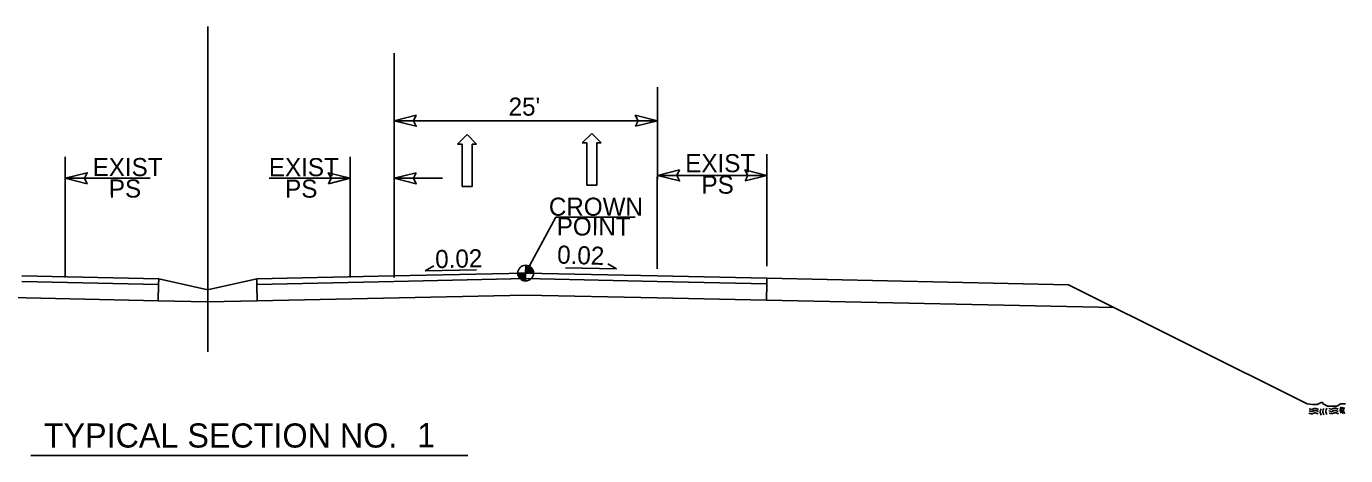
# Model space of a CAD drawing. Extents: x 2241081 to 2251104, y 658534 to 663427.
# Drawn here: x 2241521 to 2242122, y 662176 to 662372 of the extents above; entities that cross this region are included whole.
import ezdxf

# ---------------------------------------------------------------- set-up
doc = ezdxf.new("R2010")
doc.units = 0
for name, color, linetype in [('Old_Level_1', 7, 'Continuous'), ('Old_Level_2', 7, 'Continuous'), ('Prop Dimension Text', 7, 'Continuous'), ('Prop Lane Arrow CELL', 7, 'Continuous'), ('Typical Arrow Superelevation CELL', 7, 'Continuous'), ('Typical Berm Information CELL', 7, 'Continuous'), ('Typical Grade Point Symbol CELL', 7, 'Continuous'), ('Typical Hinge Slope Interstate CELL', 7, 'Continuous'), ('Typical Terminator CELL', 7, 'Continuous'), ('Typical Text Centerline CELL', 7, 'Continuous'), ('Typical Text Grade Point CELL', 7, 'Continuous'), ('Typical Text Label CELL', 7, 'Continuous')]:
    doc.layers.add(name, color=color, linetype=linetype)

# ---------------------------------------------------------------- blocks, each defined once
blk = doc.blocks.new('TERMINATOR')
at = {"layer": 'Typical Terminator CELL'}
blk.add_lwpolyline([(-0.469, 0.081), (0, 0), (-0.471, -0.083), (-0.411, 0)], close=True, dxfattribs=at)

msp = doc.modelspace()

# ---------------------------------------------------------------- linework, layer by layer
at = {"layer": 'Old_Level_1'}
for p, q in [((2241581.23, 662256.58), (2241603.63, 662251.64)), ((2241625.93, 662256.58), (2241603.53, 662251.64))]:
    msp.add_line(p, q, dxfattribs=at)
msp.add_lwpolyline([(2242104.86, 662199.5), (2242107.33, 662199.19), (2242107.94, 662199.19), (2242108.87, 662199.19), (2242109.48, 662199.19), (2242110.1, 662199.5), (2242110.72, 662199.81), (2242111.33, 662200.11), (2242111.95, 662200.11), (2242112.26, 662199.5), (2242112.87, 662199.19), (2242113.49, 662198.88), (2242114.11, 662198.57), (2242114.72, 662198.57), (2242115.34, 662198.57), (2242115.95, 662198.57), (2242116.57, 662198.57), (2242117.19, 662198.57), (2242117.8, 662198.57), (2242118.42, 662198.57), (2242119.03, 662198.88), (2242119.65, 662199.19), (2242120.27, 662199.5), (2242121.19, 662199.5), (2242121.81, 662199.5), (2242122.42, 662199.5)], dxfattribs=at)
at = {"layer": 'Old_Level_2'}
for p, q in [((2241518.84, 662257.92), (2241581.23, 662256.58)), ((2241581.23, 662256.58), (2241581.18, 662254.08)), ((2241688.32, 662257.92), (2241625.93, 662256.58)), ((2241625.93, 662256.58), (2241625.98, 662254.08)), ((2241748.54, 662259.21), (2241688.32, 662257.92)), ((2241748.59, 662256.71), (2241688.37, 662255.42)), ((2241748.49, 662256.71), (2241808.54, 662255.42)), ((2241748.54, 662259.21), (2241808.54, 662257.92)), ((2241808.54, 662257.92), (2241858.54, 662256.85)), ((2241858.54, 662256.85), (2241858.48, 662254.35)), ((2241858.54, 662256.85), (2241996.04, 662253.91)), ((2241518.79, 662255.42), (2241581.18, 662254.08)), ((2241581.02, 662246.59), (2241581.18, 662254.08)), ((2241688.37, 662255.42), (2241625.98, 662254.08)), ((2241626.14, 662246.59), (2241625.98, 662254.08)), ((2241808.54, 662255.42), (2241858.48, 662254.35)), ((2241858.32, 662246.85), (2241858.48, 662254.35)), ((2241458.63, 662249.21), (2241581.02, 662246.59)), ((2241581.02, 662246.59), (2241603.58, 662246.1)), ((2241626.14, 662246.59), (2241603.58, 662246.1)), ((2241748.53, 662249.21), (2241626.14, 662246.59)), ((2241748.53, 662249.21), (2241808.53, 662247.92)), ((2241808.53, 662247.92), (2241858.32, 662246.85)), ((2241858.32, 662246.85), (2242016.93, 662243.46))]:
    msp.add_line(p, q, dxfattribs=at)
for points in [[(2242109.84, 662194.99), (2242108.34, 662195.41), (2242106.75, 662195.01), (2242105.6, 662195.27)], [(2242109.99, 662196.08), (2242108.49, 662196.51), (2242106.9, 662196.1), (2242105.75, 662196.36)], [(2242109.99, 662196.08), (2242108.49, 662196.51), (2242106.9, 662196.1), (2242105.75, 662196.36)], [(2242110.03, 662197.02), (2242108.53, 662197.45), (2242106.94, 662197.04), (2242105.79, 662197.3)], [(2242110.03, 662197.02), (2242108.53, 662197.45), (2242106.94, 662197.04), (2242105.79, 662197.3)], [(2242111.28, 662197.31), (2242110.85, 662196.06), (2242111.31, 662194.42)], [(2242111.28, 662197.31), (2242110.85, 662196.06), (2242111.31, 662194.42)], [(2242112.49, 662197.42), (2242112.07, 662196.17), (2242112.52, 662194.52)], [(2242112.49, 662197.42), (2242112.07, 662196.17), (2242112.52, 662194.52)], [(2242113.8, 662197.52), (2242113.39, 662196.28), (2242113.83, 662194.63)], [(2242113.8, 662197.52), (2242113.39, 662196.28), (2242113.83, 662194.63)], [(2242119.06, 662197.16), (2242117.56, 662197.6), (2242115.97, 662197.19), (2242114.83, 662197.45)], [(2242119.06, 662197.16), (2242117.56, 662197.6), (2242115.97, 662197.19), (2242114.83, 662197.45)], [(2242119.07, 662196.12), (2242117.56, 662196.54), (2242115.98, 662196.14), (2242114.84, 662196.39)], [(2242119.07, 662196.12), (2242117.56, 662196.54), (2242115.98, 662196.14), (2242114.84, 662196.39)], [(2242119.19, 662195.06), (2242117.68, 662195.48), (2242116.09, 662195.09), (2242114.94, 662195.34)], [(2242119.19, 662195.06), (2242117.68, 662195.48), (2242116.09, 662195.09), (2242114.94, 662195.34)], [(2242120.39, 662198.13), (2242119.96, 662196.89), (2242120.42, 662195.24)], [(2242120.39, 662198.13), (2242119.96, 662196.89), (2242120.42, 662195.24)], [(2242121.17, 662198.05), (2242120.75, 662196.81), (2242121.21, 662195.16)], [(2242121.17, 662198.05), (2242120.75, 662196.81), (2242121.21, 662195.16)], [(2242121.9, 662197.91), (2242121.48, 662196.67), (2242121.93, 662195.02)], [(2242121.9, 662197.91), (2242121.48, 662196.67), (2242121.93, 662195.02)]]:
    msp.add_spline(points, degree=3, dxfattribs=at)
at = {"layer": 'Prop Dimension Text'}
for p, q in [((2241688.54, 662257.22), (2241688.6, 662359.56)), ((2241808.54, 662262.36), (2241808.59, 662343.98)), ((2241808.54, 662261.11), (2241808.59, 662342.73)), ((2241688.58, 662328.74), (2241748.58, 662328.7)), ((2241748.58, 662328.7), (2241808.58, 662328.66)), ((2241538.63, 662257.23), (2241538.59, 662312.31)), ((2241668.54, 662257.23), (2241668.57, 662312.31)), ((2241858.54, 662262.33), (2241858.57, 662313.44)), ((2241808.69, 662303.78), (2241858.57, 662303.75)), ((2241538.6, 662302.48), (2241577.29, 662302.5)), ((2241668.57, 662302.48), (2241631.62, 662302.5)), ((2241710.63, 662302.45), (2241688.57, 662302.47))]:
    msp.add_line(p, q, dxfattribs=at)
at = {"layer": 'Prop Lane Arrow CELL'}
for p, q in [((2241721.89, 662322.42), (2241717.48, 662318.08)), ((2241726.16, 662318.07), (2241721.89, 662322.42)), ((2241778.73, 662322.95), (2241774.32, 662318.61)), ((2241783, 662318.61), (2241778.73, 662322.95)), ((2241717.48, 662318.08), (2241719.54, 662318.08)), ((2241719.54, 662318.08), (2241719.53, 662298.78)), ((2241724.08, 662298.78), (2241724.09, 662318.08)), ((2241724.09, 662318.08), (2241726.16, 662318.07)), ((2241774.32, 662318.61), (2241776.38, 662318.61)), ((2241776.38, 662318.61), (2241776.37, 662299.31)), ((2241780.92, 662299.31), (2241780.93, 662318.61)), ((2241780.93, 662318.61), (2241783, 662318.61)), ((2241719.53, 662298.78), (2241724.08, 662298.78)), ((2241776.37, 662299.31), (2241780.92, 662299.31))]:
    msp.add_line(p, q, dxfattribs=at)
at = {"layer": 'Typical Arrow Superelevation CELL'}
for p, q in [((2241702.79, 662260.22), (2241706.7, 662262.59)), ((2241789.94, 662261.14), (2241766.64, 662261.61)), ((2241789.94, 662261.14), (2241786.03, 662263.51)), ((2241702.79, 662260.22), (2241726.09, 662260.69))]:
    msp.add_line(p, q, dxfattribs=at)
at = {"layer": 'Typical Grade Point Symbol CELL'}
for p, q in [((2241748.54, 662259.21), (2241762.31, 662284.76)), ((2241748.55, 662262.79), (2241748.54, 662259.21)), ((2241748.54, 662259.21), (2241748.55, 662262.79)), ((2241744.96, 662259.21), (2241748.54, 662259.21)), ((2241748.54, 662259.21), (2241748.54, 662255.63)), ((2241752.12, 662259.21), (2241748.54, 662259.21))]:
    msp.add_line(p, q, dxfattribs=at)
for points in [[(2241748.59, 662259.21), (2241748.59, 662262.79), (2241748.59, 662262.79)], [(2241748.67, 662259.21), (2241748.67, 662262.79)], [(2241748.74, 662259.21), (2241748.74, 662262.78)], [(2241748.81, 662259.21), (2241748.81, 662262.78)], [(2241748.88, 662259.21), (2241748.88, 662262.77)], [(2241748.95, 662259.21), (2241748.95, 662262.76)], [(2241749.02, 662259.21), (2241749.02, 662262.76)], [(2241749.1, 662259.21), (2241749.1, 662262.74)], [(2241749.17, 662259.21), (2241749.17, 662262.73)], [(2241749.24, 662259.21), (2241749.24, 662262.72)], [(2241749.31, 662259.21), (2241749.31, 662262.7)], [(2241749.38, 662259.21), (2241749.38, 662262.68)], [(2241749.45, 662259.21), (2241749.45, 662262.67)], [(2241749.53, 662259.21), (2241749.53, 662262.65)], [(2241749.6, 662259.21), (2241749.6, 662262.63)], [(2241749.67, 662259.21), (2241749.67, 662262.61)], [(2241749.74, 662259.21), (2241749.74, 662262.58)], [(2241749.81, 662259.21), (2241749.81, 662262.56)], [(2241749.88, 662259.21), (2241749.88, 662262.53)], [(2241749.96, 662259.21), (2241749.96, 662262.49)], [(2241750.03, 662259.21), (2241750.03, 662262.46)], [(2241750.1, 662259.21), (2241750.1, 662262.43)], [(2241750.17, 662259.21), (2241750.17, 662262.4)], [(2241750.24, 662259.21), (2241750.24, 662262.36)], [(2241750.31, 662259.21), (2241750.31, 662262.32)], [(2241750.38, 662259.21), (2241750.38, 662262.28)], [(2241750.46, 662259.21), (2241750.46, 662262.23)], [(2241750.53, 662259.21), (2241750.53, 662262.18)], [(2241750.6, 662259.21), (2241750.6, 662262.14)], [(2241750.67, 662259.21), (2241750.67, 662262.09)], [(2241750.74, 662259.21), (2241750.74, 662262.03)], [(2241750.81, 662259.21), (2241750.81, 662261.98)], [(2241750.89, 662259.21), (2241750.89, 662261.91)], [(2241750.96, 662259.21), (2241750.96, 662261.85)], [(2241751.03, 662259.21), (2241751.03, 662261.79)], [(2241751.1, 662259.21), (2241751.1, 662261.71)], [(2241751.17, 662259.21), (2241751.17, 662261.63)], [(2241751.24, 662259.21), (2241751.24, 662261.55)], [(2241745, 662258.7), (2241745, 662259.21)], [(2241745.07, 662258.33), (2241745.07, 662259.21)], [(2241745.14, 662258.09), (2241745.14, 662259.21)], [(2241745.21, 662257.89), (2241745.21, 662259.21)], [(2241745.28, 662257.72), (2241745.28, 662259.21)], [(2241745.36, 662257.57), (2241745.36, 662259.21)], [(2241745.43, 662257.44), (2241745.43, 662259.21)], [(2241745.5, 662257.32), (2241745.5, 662259.21)], [(2241745.57, 662257.21), (2241745.57, 662259.21)], [(2241745.64, 662257.11), (2241745.64, 662259.21)], [(2241745.71, 662257.01), (2241745.71, 662259.21)], [(2241745.79, 662256.92), (2241745.79, 662259.21)], [(2241745.86, 662256.84), (2241745.86, 662259.21)], [(2241745.93, 662256.76), (2241745.93, 662259.21)], [(2241746, 662256.69), (2241746, 662259.21)], [(2241746.07, 662256.61), (2241746.07, 662259.21)], [(2241746.14, 662256.55), (2241746.14, 662259.21)], [(2241746.22, 662256.49), (2241746.22, 662259.21)], [(2241746.29, 662256.42), (2241746.29, 662259.21)], [(2241746.36, 662256.37), (2241746.36, 662259.21)], [(2241746.43, 662256.32), (2241746.43, 662259.21)], [(2241746.5, 662256.26), (2241746.5, 662259.21)], [(2241746.57, 662256.22), (2241746.57, 662259.21)], [(2241746.65, 662256.17), (2241746.65, 662259.21)], [(2241746.72, 662256.13), (2241746.72, 662259.21)], [(2241746.79, 662256.09), (2241746.79, 662259.21)], [(2241746.86, 662256.05), (2241746.86, 662259.21)], [(2241746.93, 662256.01), (2241746.93, 662259.21)], [(2241747, 662255.98), (2241747, 662259.21)], [(2241747.07, 662255.95), (2241747.07, 662259.21)], [(2241747.15, 662255.91), (2241747.15, 662259.21)], [(2241747.22, 662255.88), (2241747.22, 662259.21)], [(2241747.29, 662255.85), (2241747.29, 662259.21)], [(2241747.36, 662255.83), (2241747.36, 662259.21)], [(2241747.43, 662255.8), (2241747.43, 662259.21)], [(2241747.5, 662255.78), (2241747.5, 662259.21)], [(2241747.58, 662255.76), (2241747.58, 662259.21)], [(2241747.65, 662255.74), (2241747.65, 662259.21)], [(2241747.72, 662255.72), (2241747.72, 662259.21)], [(2241747.79, 662255.71), (2241747.79, 662259.21)], [(2241747.86, 662255.69), (2241747.86, 662259.21)], [(2241747.93, 662255.67), (2241747.93, 662259.21)], [(2241748.01, 662255.67), (2241748.01, 662259.21)], [(2241748.08, 662255.66), (2241748.08, 662259.21)], [(2241748.15, 662255.65), (2241748.15, 662259.21)], [(2241748.22, 662255.64), (2241748.22, 662259.21)], [(2241748.29, 662255.63), (2241748.29, 662259.21)], [(2241748.36, 662255.63), (2241748.36, 662259.21)], [(2241748.44, 662255.63), (2241748.44, 662259.21)], [(2241748.51, 662255.63), (2241748.51, 662255.63), (2241748.51, 662259.21)], [(2241751.32, 662259.21), (2241751.32, 662261.47)], [(2241751.39, 662259.21), (2241751.39, 662261.38)], [(2241751.46, 662259.21), (2241751.46, 662261.28)], [(2241751.53, 662259.21), (2241751.53, 662261.18)], [(2241751.6, 662259.21), (2241751.6, 662261.07)], [(2241751.67, 662259.21), (2241751.67, 662260.94)], [(2241751.75, 662259.21), (2241751.75, 662260.81)], [(2241751.82, 662259.21), (2241751.82, 662260.66)], [(2241751.89, 662259.21), (2241751.89, 662260.49)], [(2241751.96, 662259.21), (2241751.96, 662260.27)], [(2241752.03, 662259.21), (2241752.03, 662260.02)], [(2241752.1, 662259.21), (2241752.1, 662259.6)]]:
    msp.add_lwpolyline(points, dxfattribs=at)
msp.add_circle((2241748.54, 662259.21), 3.58, dxfattribs=at)
for start, end in [(359.99048, 89.99048), (179.99048, 269.99048)]:
    msp.add_arc((2241748.54, 662259.21), 3.58, start, end, dxfattribs=at)
at = {"layer": 'Typical Hinge Slope Interstate CELL'}
msp.add_line((2241996.04, 662253.91), (2242104.86, 662199.5), dxfattribs=at)
at = {"layer": 'Typical Text Centerline CELL'}
msp.add_line((2241603.65, 662223.22), (2241603.56, 662371.77), dxfattribs=at)
at = {"layer": 'Typical Text Grade Point CELL'}
msp.add_line((2241798.44, 662284.74), (2241762.31, 662284.76), dxfattribs=at)
at = {"layer": 'Typical Text Label CELL'}
msp.add_line((2241522.91, 662175.94), (2241722.21, 662175.94), dxfattribs=at)

# ---------------------------------------------------------------- block references
at = {"layer": 'Typical Terminator CELL'}
for p, xscale, yscale, rotation in [((2241688.58, 662328.74), 21.314641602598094, -30.59316138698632, 179.96498243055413), ((2241808.58, 662328.66), 21.314641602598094, -30.59316138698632, -0.0350175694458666), ((2241538.6, 662302.48), 21.314641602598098, 30.593161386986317, -179.96511250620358), ((2241668.57, 662302.48), 21.314641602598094, -30.59316138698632, -0.0350175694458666), ((2241688.57, 662302.47), 21.314641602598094, -30.59316138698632, 179.96498243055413), ((2241808.69, 662303.78), 21.314641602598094, -30.59316138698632, 179.96498243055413), ((2241858.57, 662303.75), 21.314641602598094, -30.59316138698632, -0.0350175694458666)]:
    msp.add_blockref('TERMINATOR', p, dxfattribs=dict(at, xscale=xscale, yscale=yscale, rotation=rotation))

# ---------------------------------------------------------------- texts
at = {"layer": 'Prop Dimension Text'}
for s, rotation, p in [("25'", 359.96498, (2241740.76, 662331.05)), ('EXIST', 0.03489, (2241551.08, 662303.44)), ('EXIST', 0.03489, (2241631.45, 662303.41)), ('EXIST', 0.03489, (2241821.31, 662305.22)), ('PS', 0.03489, (2241828.71, 662295.44)), ('PS', 0.03489, (2241558.48, 662293.67)), ('PS', 0.03489, (2241638.86, 662293.63))]:
    msp.add_text(s, height=8.25, rotation=rotation, dxfattribs=at).set_placement(p)
at = {"layer": 'Typical Berm Information CELL'}
for rotation, p in [(1.14587, (2241707.37, 662261.46)), (358.19158, (2241762.8, 662263.59))]:
    msp.add_text('0.02 ', height=8.25, rotation=rotation, dxfattribs=at).set_placement(p)
at = {"layer": 'Typical Text Grade Point CELL'}
for s, p in [('CROWN', (2241759.13, 662285.39)), ('POINT', (2241762.7, 662276.38))]:
    msp.add_text(s, height=8.25, rotation=359.96498, dxfattribs=at).set_placement(p)
at = {"layer": 'Typical Text Label CELL'}
for s, height, p in [('TYPICAL SECTION NO.  ', 11.0106, (2241528.82, 662179.62)), ('1 ', 11.011, (2241699.04, 662179.77))]:
    msp.add_text(s, height=height, dxfattribs=at).set_placement(p)

doc.saveas('drawing.dxf')
